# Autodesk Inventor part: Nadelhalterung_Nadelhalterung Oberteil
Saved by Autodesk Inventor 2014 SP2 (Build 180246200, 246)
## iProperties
Created: 2015-07
Part Number: Nadelhalterung_Nadelhalterung Oberteil
Material: Generisch
Document SubType Name: Modeling
Designer: e_krauts
Density: 1 g/cm^3
Appearance: Vorgabe
Mass: 7.61003 g
Surface Area: 35.8794 cm^2
Volume: 7.61003 cm^3
Sending System: SolidWorks 2011
Last Author: e_boekem
Erstellt durch: XYZ
Werkstoff: AlCu4PbMg
Einheit: Stck.
Author: e_krauts
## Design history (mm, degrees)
node "Nadelhalterung_Nadelhalterung Oberteil.ipt1"
node "Schnitt-Linear austragen1"
node "Basis1"
